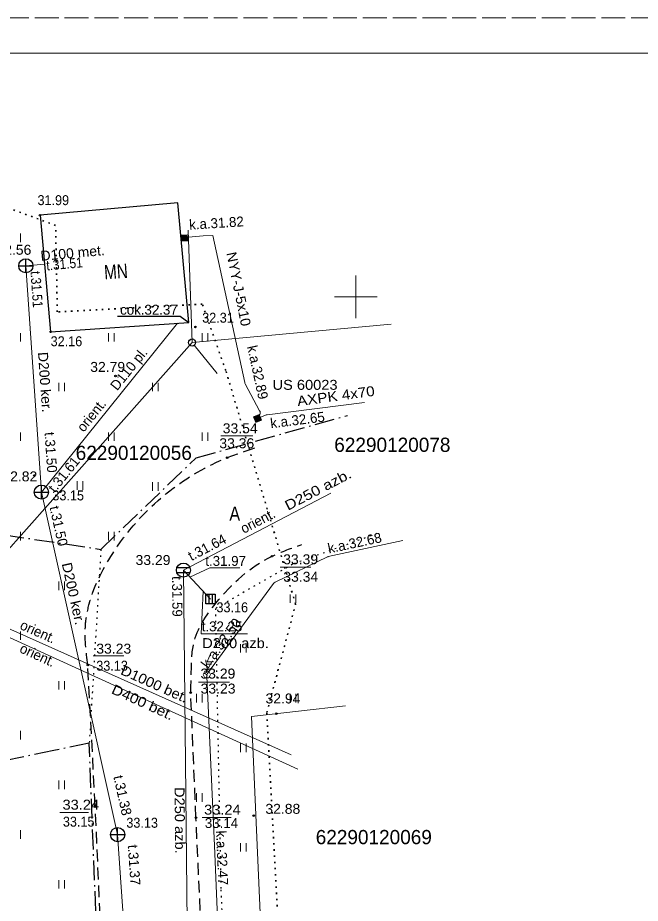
# Model space of a CAD drawing. Extents: x 380758 to 381729, y 283236 to 283533.
# Drawn here: x 381026.2 to 381070, y 283407.3 to 283469.6 of the extents above; entities that cross this region are included whole.
import ezdxf
from ezdxf.enums import TextEntityAlignment as Align

# ---------------------------------------------------------------- set-up
doc = ezdxf.new("R2010")
doc.units = 0
doc.header["$LTSCALE"] = 0.28
for name, pattern in [('DOT_DASHED', [7.7, 5, -1.2, 0.3, -1.2]), ('DOTTED', [1.5, 0.3, -1.2]), ('LONG_DASHED', [7.5, 6, -1.5]), ('MEDIUM_DASHED', [4.5, 3, -1.5])]:
    doc.linetypes.add(name, pattern=pattern)
for name, color, linetype, lineweight in [('11', 7, 'Continuous', 13), ('12', 7, 'Continuous', 13), ('18', 7, 'Continuous', 13), ('23', 7, 'Continuous', 13), ('25', 7, 'DOTTED', 35), ('29', 7, 'DOT_DASHED', 25), ('30', 7, 'Continuous', 13), ('35', 7, 'Continuous', 13), ('37', 7, 'MEDIUM_DASHED', 13), ('38', 7, 'Continuous', 25), ('4', 7, 'Continuous', 13), ('40', 7, 'Continuous', 25), ('42', 7, 'Continuous', 13), ('47', 7, 'Continuous', 13), ('48', 7, 'Continuous', 25), ('58', 7, 'Continuous', 25), ('63', 7, 'Continuous', 13), ('7', 7, 'Continuous', 13)]:
    doc.layers.add(name, color=color, linetype=linetype, lineweight=lineweight)
doc.layers.add('59', color=7, linetype='Continuous')

msp = doc.modelspace()

# ---------------------------------------------------------------- hatches: boundary and pattern name
at = {"layer": '18'}
for points in [[(381038.161, 283453.936), (381037.715, 283453.907), (381037.687, 283454.346), (381038.133, 283454.375)], [(381043.365, 283441.318), (381042.95, 283441.15), (381042.785, 283441.558), (381043.2, 283441.726)]]:
    msp.add_hatch(color=256, dxfattribs=at).paths.add_polyline_path(points)

# ---------------------------------------------------------------- linework, layer by layer
at = {"layer": '11'}
for p, q in [((381037.862, 283430.768), (381048.25, 283436.178)), ((381014.238, 283431.706), (381045.443, 283417.762)), ((381037.862, 283430.768), (381039.77, 283428.726)), ((381037.862, 283430.768), (381038.232, 283394.477)), ((381017.672, 283429.628), (381045.928, 283416.755))]:
    msp.add_line(p, q, dxfattribs=at)
for points in [[(381041.824, 283430.927), (381039.718, 283430.927), (381038.321, 283430.276)], [(381042.379, 283426.294), (381039.116, 283426.294), (381039.248, 283429.285)]]:
    msp.add_lwpolyline(points, dxfattribs=at)
at = {"layer": '12'}
msp.add_line((381039.529, 283423.715), (381039.77, 283423.854), dxfattribs=at)
msp.add_lwpolyline([(381039.778, 283424.877), (381039.529, 283424.314), (381039.865, 283424.314), (381039.529, 283423.715), (381039.507, 283423.985)], dxfattribs=at)
msp.add_lwpolyline([(381039.373, 283423.185), (381039.639, 283423.185), (381039.772, 283423.415), (381039.639, 283423.646), (381039.373, 283423.646), (381039.24, 283423.415)], close=True, dxfattribs=at)
at = {"layer": '18'}
for p, q in [((381038.468, 283446.784), (381038.199, 283454.687)), ((381040.247, 283444.616), (381038.627, 283446.591))]:
    msp.add_line(p, q, dxfattribs=at)
for points in [[(381038.161, 283453.936), (381037.715, 283453.907), (381037.687, 283454.346), (381038.133, 283454.375)], [(381043.365, 283441.318), (381042.95, 283441.15), (381042.785, 283441.558), (381043.2, 283441.726)]]:
    msp.add_lwpolyline(points, close=True, dxfattribs=at)
msp.add_lwpolyline([(381013.446, 283418.625), (381038.468, 283446.784), (381052.48, 283448.067)], dxfattribs=at)
at = {"layer": '18', "lineweight": 25}
msp.add_circle((381038.4683, 283446.7841), 0.25, dxfattribs=at)
at = {"layer": '23'}
for p, q in [((381026.385, 283453.855), (381026.385, 283454.455)), ((381026.385, 283446.855), (381026.385, 283447.455)), ((381032.585, 283446.855), (381032.585, 283447.455)), ((381032.985, 283446.855), (381032.985, 283447.455)), ((381039.185, 283446.855), (381039.185, 283447.455)), ((381039.585, 283446.855), (381039.585, 283447.455)), ((381029.085, 283443.355), (381029.085, 283443.955)), ((381029.485, 283443.355), (381029.485, 283443.955)), ((381035.685, 283443.355), (381035.685, 283443.955)), ((381036.085, 283443.355), (381036.085, 283443.955)), ((381026.385, 283439.855), (381026.385, 283440.455)), ((381032.585, 283439.855), (381032.585, 283440.455)), ((381032.985, 283439.855), (381032.985, 283440.455)), ((381039.185, 283439.855), (381039.185, 283440.455)), ((381039.585, 283439.855), (381039.585, 283440.455)), ((381030.386, 283436.424), (381030.386, 283437.024)), ((381030.786, 283436.424), (381030.786, 283437.024)), ((381035.685, 283436.355), (381035.685, 283436.955)), ((381036.085, 283436.355), (381036.085, 283436.955)), ((381026.385, 283432.855), (381026.385, 283433.455)), ((381032.585, 283432.855), (381032.585, 283433.455)), ((381032.985, 283432.855), (381032.985, 283433.455)), ((381029.085, 283429.355), (381029.085, 283429.955)), ((381029.485, 283429.355), (381029.485, 283429.955)), ((381045.377, 283428.461), (381045.377, 283429.061)), ((381045.777, 283428.461), (381045.777, 283429.061)), ((381026.385, 283425.855), (381026.385, 283426.455)), ((381041.877, 283424.961), (381041.877, 283425.561)), ((381042.277, 283424.961), (381042.277, 283425.561)), ((381029.085, 283422.355), (381029.085, 283422.955)), ((381029.485, 283422.355), (381029.485, 283422.955)), ((381038.777, 283421.461), (381038.777, 283422.061)), ((381039.177, 283421.461), (381039.177, 283422.061)), ((381045.377, 283421.461), (381045.377, 283422.061)), ((381045.777, 283421.461), (381045.777, 283422.061)), ((381026.385, 283418.855), (381026.385, 283419.455)), ((381041.877, 283417.961), (381041.877, 283418.561)), ((381042.277, 283417.961), (381042.277, 283418.561)), ((381029.085, 283415.355), (381029.085, 283415.955)), ((381029.485, 283415.355), (381029.485, 283415.955)), ((381038.777, 283414.461), (381038.777, 283415.061)), ((381039.177, 283414.461), (381039.177, 283415.061)), ((381026.385, 283411.855), (381026.385, 283412.455)), ((381041.877, 283410.961), (381041.877, 283411.561)), ((381042.277, 283410.961), (381042.277, 283411.561)), ((381029.085, 283408.355), (381029.085, 283408.955)), ((381029.485, 283408.355), (381029.485, 283408.955))]:
    msp.add_line(p, q, dxfattribs=at)
at = {"layer": '25'}
for points in [[(381043.733, 283420.739), (381045.761, 283428.367), (381040.844, 283444.815), (381039.184, 283449.49), (381028.98, 283448.936), (381028.857, 283455.027), (381023.201, 283457.118), (380999.596, 283457.303), (380984.809, 283460.54)], [(381378.132, 283376.241), (381330.368, 283370.09), (381282.589, 283365.052), (381241.341, 283362.776), (381227.597, 283363.335), (381201.225, 283361.612), (381131.764, 283357.382), (381089.163, 283355.29), (381056.824, 283352.96), (381046.619, 283367.047), (381043.733, 283420.739)]]:
    msp.add_lwpolyline(points, dxfattribs=at)
at = {"layer": '29', "linetype": 'DOTTED'}
msp.add_line((381032.048, 283432.228), (381031.228, 283418.59), dxfattribs=at)
at = {"layer": '29'}
for p, q in [((381028.744, 283418.07), (381007.404, 283413.604)), ((381031.228, 283418.59), (381028.744, 283418.07))]:
    msp.add_line(p, q, dxfattribs=at)
for points in [[(381023.37, 283455.798), (381020.935, 283433.908), (381032.048, 283432.228)], [(381032.048, 283432.228), (381038.761, 283438.675), (381049.422, 283441.655)], [(381044.752, 283340.119), (381034.334, 283339.485), (381031.228, 283418.59)]]:
    msp.add_lwpolyline(points, dxfattribs=at)
at = {"layer": '29', "linetype": 'DOTTED'}
msp.add_lwpolyline([(381051.477, 283433.334), (381045.543, 283431.176), (381040.109, 283428.07), (381040.497, 283408.271), (381042.05, 283372.167), (381044.752, 283340.119)], dxfattribs=at)
at = {"layer": '30'}
for points in [[(381050, 283451.5), (381050, 283450), (381050, 283448.5)], [(381048.5, 283450), (381050, 283450), (381051.5, 283450)]]:
    msp.add_lwpolyline(points, dxfattribs=at)
at = {"layer": '35'}
msp.add_lwpolyline([(381049.28, 283421.224), (381042.652, 283420.457), (381044.312, 283382.671)], dxfattribs=at)
at = {"layer": '37', "lineweight": 25}
for points in [[(381034.551, 283344.881), (381034.032, 283356.434), (381033.527, 283370.859), (381032.933, 283385.788), (381032.275, 283400.191), (381031.647, 283414.208), (381031.126, 283424.091)], [(381042.564, 283341.713), (381041.412, 283356.761), (381040.728, 283370.945), (381039.991, 283386.538), (381039.347, 283400.52), (381038.74, 283413.344), (381038.376, 283422.148)]]:
    msp.add_lwpolyline(points, dxfattribs=at)
for points in [[(381031.126, 283424.091), (381030.966, 283426.955), (381031.232, 283428.402), (381033.023, 283432.163), (381036.913, 283436.355), (381040.939, 283438.68), (381043.103, 283439.433)], [(381038.376, 283422.148), (381038.416, 283423.642), (381038.588, 283425.613), (381040.144, 283428.449), (381044.104, 283431.745), (381046.204, 283432.562)]]:
    msp.add_spline(points, degree=3, dxfattribs=at)
at = {"layer": '38'}
for p, q in [((381026.762, 283451.687), (381026.762, 283452.687)), ((381026.262, 283452.187), (381027.262, 283452.187)), ((381027.856, 283435.758), (381027.856, 283436.758)), ((381027.356, 283436.258), (381028.356, 283436.258)), ((381033.228, 283411.651), (381033.228, 283412.651)), ((381032.728, 283412.151), (381033.728, 283412.151))]:
    msp.add_line(p, q, dxfattribs=at)
for centre in [(381026.762, 283452.187), (381027.856, 283436.258), (381033.228, 283412.151)]:
    msp.add_circle(centre, 0.5, dxfattribs=at)
at = {"layer": '40'}
msp.add_lwpolyline([(381027.762, 283455.744), (381028.509, 283447.534), (381038.246, 283448.19), (381037.478, 283456.628)], close=True, dxfattribs=at)
at = {"layer": '42', "lineweight": 25}
msp.add_lwpolyline([(381033.227, 283448.641), (381037.637, 283448.641), (381038.246, 283448.19)], dxfattribs=at)
at = {"layer": '47'}
for p, q in [((381026.762, 283452.187), (381028.075, 283452.306)), ((381033.228, 283412.151), (381027.856, 283436.258))]:
    msp.add_line(p, q, dxfattribs=at)
for points in [[(381026.762, 283452.187), (381027.856, 283436.258), (381037.437, 283448.136)], [(381033.228, 283412.151), (381035.498, 283379.573), (381043.031, 283331.59)]]:
    msp.add_lwpolyline(points, dxfattribs=at)
at = {"layer": '48'}
for p, q in [((381037.394, 283430.943), (381038.33, 283430.943)), ((381037.394, 283430.593), (381038.33, 283430.593)), ((381039.657, 283429.064), (381039.657, 283428.389)), ((381039.882, 283429.064), (381039.882, 283428.389))]:
    msp.add_line(p, q, dxfattribs=at)
msp.add_lwpolyline([(381039.432, 283429.064), (381040.107, 283429.064), (381040.107, 283428.389), (381039.432, 283428.389)], close=True, dxfattribs=at)
msp.add_circle((381037.862, 283430.768), 0.5, dxfattribs=at)
at = {"layer": '58', "lineweight": 13}
for p, q in [((381040.496, 283440.226), (381042.738, 283440.226)), ((381044.665, 283430.966), (381046.844, 283430.966)), ((381031.495, 283424.74), (381033.674, 283424.74)), ((381038.917, 283422.875), (381041.096, 283422.875)), ((381029.16, 283413.701), (381031.182, 283413.701)), ((381039.172, 283413.353), (381041.225, 283413.353))]:
    msp.add_line(p, q, dxfattribs=at)
at = {"layer": '58'}
for centre in [(381027.762, 283455.7441), (381038.708, 283447.8831), (381028.509, 283447.5341), (381033.076, 283444.4231), (381040.939, 283438.6801), (381027.363, 283437.4301), (381044.104, 283431.7451), (381031.126, 283424.0911), (381038.376, 283422.1481), (381044.398, 283420.6591), (381031.647, 283414.2081), (381038.74, 283413.3441), (381042.809, 283413.4911)]:
    msp.add_circle(centre, 0.0534, dxfattribs=at)
at = {"layer": '63'}
msp.add_line((380768.477, 283467.145), (381349.977, 283467.145), dxfattribs=at)
at = {"layer": '63', "linetype": 'LONG_DASHED'}
msp.add_lwpolyline([(381352.477, 283469.645), (380758.477, 283469.645), (380758.477, 283259.645), (381352.477, 283259.645)], dxfattribs=at)
at = {"layer": '7'}
for p, q in [((381042.219, 283443.87), (381043.223, 283441.981)), ((381043.761, 283441.705), (381050.608, 283442.558)), ((381053.307, 283432.844), (381048.064, 283431.723)), ((381047.996, 283431.699), (381044.322, 283429.921)), ((381044.211, 283429.829), (381039.559, 283423.49))]:
    msp.add_line(p, q, dxfattribs=at)
for points in [[(381037.695, 283454.146), (381039.261, 283454.288), (381039.933, 283454.323), (381042.177, 283443.97)], [(381043.245, 283441.719), (381043.075, 283441.438), (381043.686, 283441.685)], [(381039.501, 283423.299), (381040.054, 283411.364), (381040.846, 283392.306), (381041.931, 283368.727), (381042.976, 283345.438)]]:
    msp.add_lwpolyline(points, dxfattribs=at)
for centre, radius, start, end in [((381042.4705, 283444.0333), 0.3, 192.23117, 213.01093), ((381043.045, 283441.8343), 0.2307, 330.10759, 39.37803), ((381043.7981, 283441.4072), 0.3, 97.10086, 112.04528), ((381048.1271, 283431.4292), 0.3, 102.06737, 115.8194), ((381044.4528, 283429.6514), 0.3, 115.8194, 143.7228), ((381039.8006, 283423.313), 0.3, 143.7228, 182.65328)]:
    msp.add_arc(centre, radius, start, end, dxfattribs=at)

# ---------------------------------------------------------------- texts
at = {"layer": '11'}
for s, rotation, width, p in [('D250 azb.', 27.512, 1.2, (381047.4978, 283436.1249)), ('D1000 bet.', 335.923, 1.1, (381035.6777, 283422.4356)), ('D400 bet.', 335.507, 1.15, (381034.8529, 283421.1514)), ('D250 azb.', 270.584, 1.1, (381037.2601, 283413.1521))]:
    msp.add_text(s, height=0.7, rotation=rotation, dxfattribs=dict(at, width=width)).set_placement(p, align=Align.CENTER)
for s, rotation, p in [('orient.', 27.512, (381043.2628, 283433.9203)), ('t.31.64', 27.512, (381039.6873, 283432.0576)), ('t.31.59', 270.584, (381037.0715, 283428.9116)), ('orient.', 335.923, (381027.4737, 283426.1197)), ('orient.', 335.507, (381027.4449, 283424.4734))]:
    msp.add_text(s, height=0.7, rotation=rotation, dxfattribs=at).set_placement(p, align=Align.CENTER)
for s, p in [('t.31.97', (381040.8335, 283431.066)), ('t.32.25', (381040.5795, 283426.456))]:
    msp.add_text(s, height=0.7, dxfattribs=at).set_placement(p, align=Align.CENTER)
at = {"layer": '11', "width": 1.1}
msp.add_text('D200 azb.', height=0.7, dxfattribs=at).set_placement((381041.529, 283425.279), align=Align.CENTER)
at = {"layer": '37', "width": 0.85}
msp.add_text('A', height=1, dxfattribs=at).set_placement((381041.4755, 283434.243), align=Align.CENTER)
at = {"layer": '38'}
for s, width, p in [('32.56', 1.05, (381024.691, 283452.963)), ('33.15', 0.95, (381028.632, 283435.675)), ('33.13', 0.95, (381033.842, 283412.636))]:
    msp.add_text(s, height=0.7, dxfattribs=dict(at, width=width)).set_placement(p)
at = {"layer": '4', "width": 0.8}
msp.add_text('MN', height=1, rotation=3.854, dxfattribs=at).set_placement((381032.311, 283451.228))
at = {"layer": '42'}
msp.add_text('cok.32.37', height=0.7, dxfattribs=at).set_placement((381033.401, 283448.744))
at = {"layer": '47'}
for s, rotation, width, p in [('D100 met.', 5.199, 1.05, (381030.0873, 283452.7361)), ('t.31.51', 5.199, 0.9, (381029.5143, 283451.9678)), ('t.31.51', 273.929, 0.9, (381027.178, 283450.507)), ('D200 ker.', 273.929, 1.05, (381027.7638, 283443.9705)), ('D200 ker.', 282.563, 1.1, (381029.7727, 283429.0381))]:
    msp.add_text(s, height=0.7, rotation=rotation, dxfattribs=dict(at, width=width)).set_placement(p, align=Align.CENTER)
for s, rotation, p in [('D110 pl.', 51.107, (381034.2878, 283444.7077)), ('orient.', 51.107, (381031.6533, 283441.4432)), ('t.31.50', 273.929, (381028.1766, 283439.0325)), ('t.31.61', 51.107, (381029.7109, 283437.2832)), ('t.31.50', 282.563, (381028.736, 283433.7991)), ('t.31.38', 282.563, (381033.2337, 283414.8381)), ('t.31.37', 273.986, (381034.0405, 283409.9888))]:
    msp.add_text(s, height=0.7, rotation=rotation, dxfattribs=at).set_placement(p, align=Align.CENTER)
at = {"layer": '48'}
for s, width, p in [('33.29', 1.05, (381034.49, 283431.129)), ('33.16', 0.95, (381040.186, 283427.799))]:
    msp.add_text(s, height=0.7, dxfattribs=dict(at, width=width)).set_placement(p)
at = {"layer": '58'}
for s, width, p in [('31.99', 0.95, (381027.584, 283456.455)), ('32.31', 0.95, (381039.182, 283448.179)), ('32.16', 0.95, (381028.509, 283446.525)), ('32.79', 1.05, (381031.297, 283444.719)), ('33.54', 1.05, (381040.628, 283440.399)), ('33.36', 1.05, (381040.388, 283439.347)), ('32.82', 1.05, (381025.11, 283437.014)), ('33.39', 1.05, (381044.885, 283431.18)), ('33.34', 1.05, (381044.893, 283429.949)), ('33.23', 1.05, (381031.724, 283424.891)), ('33.13', 0.95, (381031.724, 283423.689)), ('33.29', 1.05, (381039.057, 283423.138)), ('33.23', 1.05, (381039.07, 283422.082)), ('32.94', 1.05, (381043.64, 283421.385)), ('33.24', 1.1, (381029.345, 283413.91)), ('33.24', 1.1, (381039.315, 283413.559)), ('32.88', 1.05, (381043.63, 283413.617)), ('33.15', 0.95, (381029.372, 283412.714))]:
    msp.add_text(s, height=0.7, dxfattribs=dict(at, width=width)).set_placement(p)
msp.add_text('33.14', height=0.7, dxfattribs=at).set_placement((381039.37, 283412.616))
at = {"layer": '59'}
for s, p in [('62290120078', (381048.483, 283439.089)), ('62290120056', (381030.273, 283438.522)), ('62290120069', (381047.177, 283411.48))]:
    msp.add_text(s, height=1, dxfattribs=at).set_placement(p)
at = {"layer": '7'}
for s, rotation, p in [('k.a.31.82', 3.593, (381038.287, 283454.725)), ('k.a.32.89', 282.231, (381042.342, 283446.495)), ('k.a.32.65', 7.101, (381044.023, 283440.752)), ('k.a.32.68', 12.067, (381048.11, 283431.939)), ('k.a.32.47', 272.38, (381040.155, 283412.423))]:
    msp.add_text(s, height=0.7, rotation=rotation, dxfattribs=at).set_placement(p)
for s, rotation, width, p in [('NYY-J-5x10', 281.47, 1.05, (381040.882, 283453.078)), ('AXPK 4x70', 7.768, 1.15, (381045.915, 283442.303)), ('k.a.32.50', 53.723, 1.05, (381039.598, 283423.792))]:
    msp.add_text(s, height=0.7, rotation=rotation, dxfattribs=dict(at, width=width)).set_placement(p)
at = {"layer": '7', "width": 1.1}
msp.add_text('US 60023', height=0.7, dxfattribs=at).set_placement((381044.135, 283443.457))

doc.saveas('drawing.dxf')
